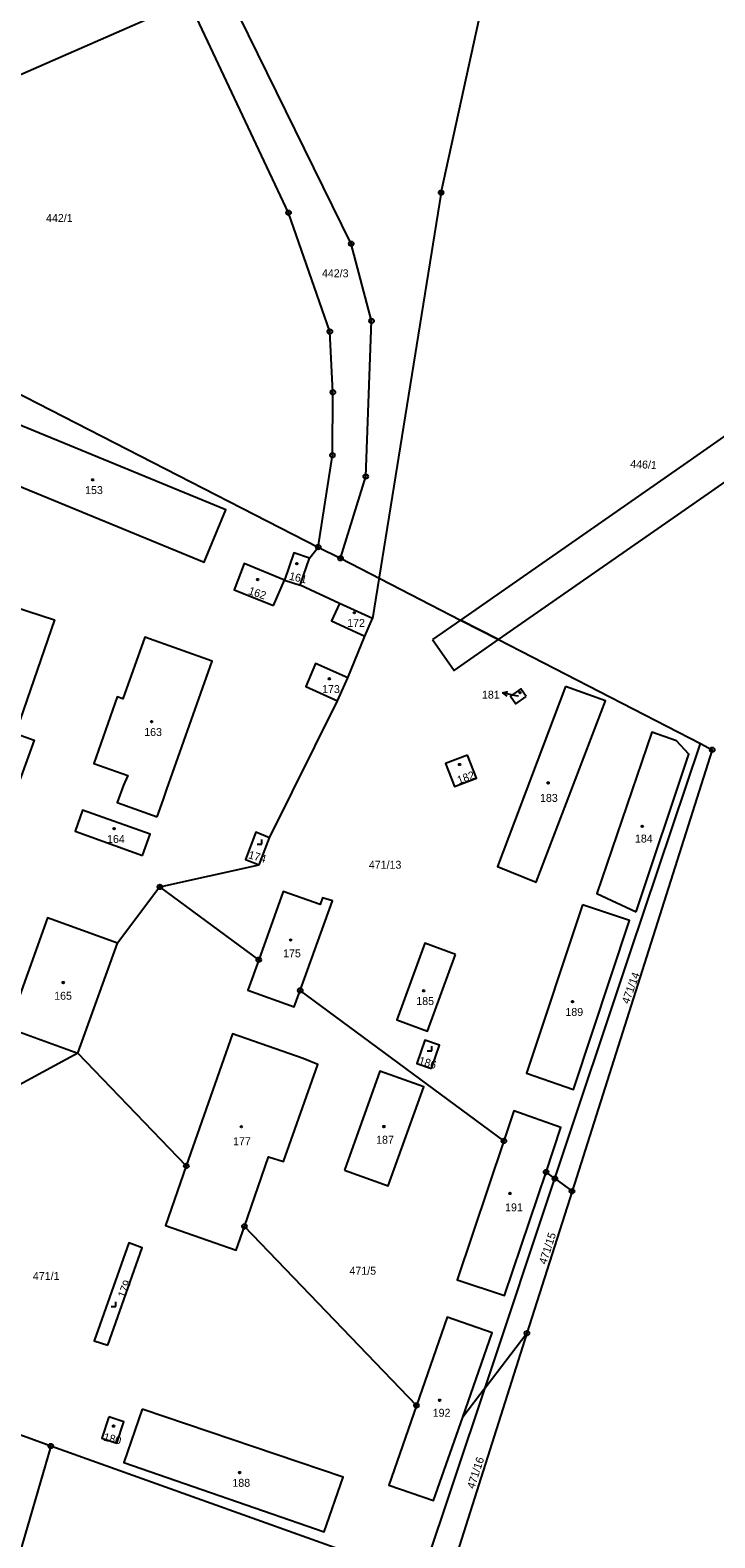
# Model space of a CAD drawing. Extents: x -758582 to -751794, y -998770 to -994350.
# Drawn here: x -753868 to -753721.4, y -996932.8 to -996610.1 of the extents above; entities that cross this region are included whole.
import ezdxf

# ---------------------------------------------------------------- set-up
doc = ezdxf.new("R2010")
doc.units = 0
for name, color, linetype in [('Hranice parcel', 7, 'Continuous'), ('Parcelní čísla', 7, 'Continuous'), ('Pop  PČ popisy', 7, 'Continuous'), ('Poz předměty', 7, 'Continuous'), ('Věcná břemena k části', 7, 'Continuous'), ('Značky bodu BP', 7, 'Continuous'), ('Značky budov', 7, 'Continuous'), ('Značky kultur', 7, 'Continuous')]:
    doc.layers.add(name, color=color, linetype=linetype)

msp = doc.modelspace()

# ---------------------------------------------------------------- linework, layer by layer
at = {"layer": 'Hranice parcel'}
for p, q in [((-753834.03, -996603.91), (-753942.18, -996651.11)), ((-753874.54, -996685.76), (-753806.31, -996720.72)), ((-753810.18, -996728.89), (-753808.19, -996723.09)), ((-753808.19, -996723.09), (-753806.31, -996720.72)), ((-753806.31, -996720.72), (-753801.53, -996723.13)), ((-753801.73, -996732.82), (-753810.18, -996728.89)), ((-753800.01, -996748.75), (-753796.35, -996739.83)), ((-753802.2, -996753.65), (-753800.01, -996748.75)), ((-753816.73, -996782.97), (-753802.2, -996753.65)), ((-753818.95, -996788.72), (-753816.73, -996782.97)), ((-753840.2, -996793.46), (-753818.95, -996788.72)), ((-753840.2, -996793.46), (-753849.28, -996805.48)), ((-753819.06, -996809.07), (-753840.2, -996793.46)), ((-753857.78, -996829.03), (-753849.28, -996805.48)), ((-753766.58, -996847.84), (-753810.18, -996815.63)), ((-753857.78, -996829.03), (-753878.25, -996840.12)), ((-753834.55, -996853.2), (-753857.78, -996829.03)), ((-753755.66, -996855.91), (-753757.56, -996854.5)), ((-753770.6, -996900.68), (-753755.66, -996855.91)), ((-753752, -996858.61), (-753761.65, -996888.99)), ((-753755.66, -996855.91), (-753752, -996858.61)), ((-753785.3, -996904.45), (-753822.12, -996866.13)), ((-753770.6, -996900.68), (-753761.65, -996888.99)), ((-753784.22, -996941.5), (-753770.6, -996900.68)), ((-753770.6, -996900.68), (-753775.4, -996906.94)), ((-753863.56, -996913.15), (-753870.24, -996936.23)), ((-753784.22, -996941.5), (-753863.56, -996913.15))]:
    msp.add_line(p, q, dxfattribs=at)
for points in [[(-753801.53, -996723.13), (-753796.14, -996705.63), (-753794.91, -996672.33), (-753799.24, -996655.8), (-753845.29, -996562.1), (-753839.59, -996551.34)], [(-753806.31, -996720.72), (-753803.27, -996701.08), (-753803.18, -996687.6), (-753803.83, -996674.61), (-753812.65, -996649.16), (-753834.03, -996603.91)], [(-753889.23, -996699.92), (-753830.74, -996723.97), (-753826.13, -996712.75), (-753884.62, -996688.69), (-753889.23, -996699.92)], [(-753808.19, -996723.09), (-753811.52, -996721.94), (-753813.53, -996727.81), (-753810.18, -996728.89)], [(-753815.91, -996733.25), (-753813.53, -996727.81), (-753822.14, -996724.23), (-753824.33, -996729.87), (-753815.91, -996733.25)], [(-753801.53, -996723.13), (-753775.87, -996736.35), (-753767.74, -996740.53), (-753724.52, -996762.8)], [(-753884.65, -996751.21), (-753884.11, -996749.42), (-753882.15, -996750.09), (-753879.74, -996743.09), (-753878.28, -996743.59), (-753874.47, -996732.5), (-753862.77, -996736.34), (-753870.13, -996757.67), (-753872.4, -996756.89), (-753873.24, -996759.88), (-753867.14, -996762.07), (-753871.44, -996774.09), (-753890.56, -996767.28), (-753889.05, -996763.12)], [(-753801.73, -996732.82), (-753803.46, -996736.51), (-753796.35, -996739.83)], [(-753796.35, -996739.83), (-753794.72, -996736), (-753801.73, -996732.82)], [(-753840.78, -996778.45), (-753839.44, -996774.66), (-753838.71, -996772.58), (-753829.04, -996745.13), (-753843.45, -996740.03), (-753848.12, -996753.2), (-753849.35, -996752.77), (-753854.33, -996767.03), (-753847.07, -996769.63), (-753847.97, -996771.66), (-753849.32, -996775.44), (-753840.78, -996778.45)], [(-753800.01, -996748.75), (-753806.89, -996745.62), (-753809, -996750.6), (-753802.2, -996753.65)], [(-753753.4, -996750.56), (-753767.96, -996789.12), (-753759.66, -996792.45), (-753744.81, -996753.64), (-753753.4, -996750.56)], [(-753761.8, -996752.7), (-753762.98, -996751.07), (-753765.18, -996752.66), (-753764, -996754.29), (-753761.8, -996752.7)], [(-753738.25, -996798.84), (-753726.99, -996765.04), (-753729.65, -996762.24), (-753734.9, -996760.37), (-753746.68, -996794.91), (-753738.25, -996798.84)], [(-753755.66, -996855.91), (-753739.54, -996807.6), (-753724.52, -996762.8)], [(-753724.52, -996762.8), (-753721.99, -996764.12), (-753752, -996858.61)], [(-753774.36, -996765.28), (-753779.06, -996767.05), (-753777.12, -996772.01), (-753772.44, -996770.18), (-753774.36, -996765.28)], [(-753843.9, -996786.74), (-753842.31, -996782.17), (-753856.75, -996777.05), (-753858.37, -996781.56), (-753843.9, -996786.74)], [(-753816.73, -996782.97), (-753819.68, -996781.74), (-753821.92, -996787.57), (-753818.95, -996788.72)], [(-753810.18, -996815.63), (-753803.29, -996796.45), (-753805.4, -996795.83), (-753805.91, -996797.21), (-753813.79, -996794.44), (-753819.06, -996809.07)], [(-753849.28, -996805.48), (-753864.25, -996800.1), (-753872.71, -996823.65), (-753857.78, -996829.03)], [(-753749.76, -996797.34), (-753761.74, -996833.37), (-753751.68, -996836.84), (-753739.69, -996800.65), (-753749.76, -996797.34)], [(-753776.95, -996807.95), (-753783.5, -996805.54), (-753789.49, -996821.95), (-753782.9, -996824.34), (-753776.95, -996807.95)], [(-753819.06, -996809.07), (-753821.41, -996815.58), (-753811.45, -996819.17), (-753810.18, -996815.63)], [(-753822.12, -996866.13), (-753816.97, -996851.21), (-753813.76, -996852.24), (-753806.38, -996831.47), (-753809.57, -996830.17), (-753824.66, -996824.95), (-753834.55, -996853.2)], [(-753782.06, -996832.36), (-753780.37, -996827.33), (-753783.51, -996826.25), (-753785.19, -996831.3), (-753782.06, -996832.36)], [(-753800.73, -996854.07), (-753791.36, -996857.48), (-753783.68, -996836.29), (-753793.1, -996832.88), (-753800.73, -996854.07)], [(-753757.56, -996854.5), (-753754.36, -996844.96), (-753764.42, -996841.43), (-753766.58, -996847.84)], [(-753766.58, -996847.84), (-753776.59, -996877.54), (-753766.46, -996880.94), (-753757.56, -996854.5)], [(-753834.55, -996853.2), (-753839, -996865.93), (-753823.88, -996871.2), (-753822.12, -996866.13)], [(-753851.32, -996891.54), (-753844.03, -996870.73), (-753846.87, -996869.65), (-753854.29, -996890.65), (-753851.32, -996891.54)], [(-753775.4, -996906.94), (-753769.11, -996888.89), (-753778.74, -996885.54), (-753785.3, -996904.45)], [(-753761.65, -996888.99), (-753778.93, -996943.39), (-753784.22, -996941.5)], [(-753863.56, -996913.15), (-753868.62, -996911.34), (-753884.21, -996905.77), (-753901.63, -996899.54)], [(-753851.17, -996906.89), (-753852.67, -996911.46), (-753849.43, -996912.52), (-753847.91, -996907.94), (-753851.17, -996906.89)], [(-753844, -996905.26), (-753847.9, -996916.68), (-753805.03, -996931.54), (-753801, -996919.82), (-753844, -996905.26)], [(-753785.3, -996904.45), (-753791.2, -996921.49), (-753781.61, -996924.78), (-753775.4, -996906.94)]]:
    msp.add_lwpolyline(points, dxfattribs=at)
at = {"layer": 'Pop  PČ popisy'}
for p, q in [((-753766.85, -996751.96), (-753765.77, -996751.67)), ((-753763.92, -996752.58), (-753766.85, -996751.96)), ((-753766.85, -996751.96), (-753765.98, -996752.65)), ((-753763.48, -996752.67), (-753763.92, -996752.58))]:
    msp.add_line(p, q, dxfattribs=at)
at = {"layer": 'Poz předměty'}
for q in [(-753761.33, -996559.87), (-753794.72, -996736)]:
    msp.add_line((-753780.02, -996644.86), q, dxfattribs=at)
for radius in [0.5, 0.4, 0.3, 0.2, 0.1]:
    msp.add_circle((-753780.02, -996644.86), radius, dxfattribs=at)
at = {"layer": 'Věcná břemena k části'}
for points in [[(-753775.87, -996736.35), (-753767.74, -996740.53), (-753722.77, -996709.26), (-753644.07, -996654.17), (-753591.01, -996617.57), (-753595.6, -996610.92), (-753648.69, -996647.53), (-753727.39, -996702.64)], [(-753781.83, -996740.49), (-753777.22, -996747.12), (-753767.74, -996740.53), (-753775.87, -996736.35)]]:
    msp.add_lwpolyline(points, close=True, dxfattribs=at)
at = {"layer": 'Značky bodu BP'}
for centre, radius in [((-753812.65, -996649.16), 0.5), ((-753812.65, -996649.16), 0.0303), ((-753799.24, -996655.8), 0.5), ((-753799.24, -996655.8), 0.0303), ((-753803.83, -996674.61), 0.5), ((-753803.83, -996674.61), 0.0303), ((-753794.91, -996672.33), 0.5), ((-753794.91, -996672.33), 0.0303), ((-753803.18, -996687.6), 0.5), ((-753803.18, -996687.6), 0.0303), ((-753803.27, -996701.08), 0.5), ((-753803.27, -996701.08), 0.0303), ((-753796.14, -996705.63), 0.5), ((-753796.14, -996705.63), 0.0303), ((-753806.31, -996720.72), 0.5), ((-753806.31, -996720.72), 0.0303), ((-753801.53, -996723.13), 0.5), ((-753801.53, -996723.13), 0.0303), ((-753721.99, -996764.12), 0.5), ((-753721.99, -996764.12), 0.0303), ((-753840.2, -996793.46), 0.5), ((-753840.2, -996793.46), 0.0303), ((-753819.06, -996809.07), 0.5), ((-753819.06, -996809.07), 0.0303), ((-753810.18, -996815.63), 0.5), ((-753810.18, -996815.63), 0.0303), ((-753766.58, -996847.84), 0.5), ((-753766.58, -996847.84), 0.0303), ((-753834.55, -996853.2), 0.5), ((-753834.55, -996853.2), 0.0303), ((-753757.56, -996854.5), 0.5), ((-753757.56, -996854.5), 0.0303), ((-753755.66, -996855.91), 0.5), ((-753755.66, -996855.91), 0.0303), ((-753752, -996858.61), 0.5), ((-753752, -996858.61), 0.0303), ((-753822.12, -996866.13), 0.5), ((-753822.12, -996866.13), 0.0303), ((-753761.65, -996888.99), 0.5), ((-753761.65, -996888.99), 0.0303), ((-753785.3, -996904.45), 0.5), ((-753785.3, -996904.45), 0.0303), ((-753863.56, -996913.15), 0.5), ((-753863.56, -996913.15), 0.0303)]:
    msp.add_circle(centre, radius, dxfattribs=at)
at = {"layer": 'Značky budov'}
for centre in [(-753854.58, -996706.34), (-753810.91, -996724.27), (-753819.28, -996727.69), (-753798.59, -996734.77), (-753803.93, -996748.93), (-753763.12, -996751.91), (-753841.97, -996758.12), (-753776.07, -996767.27), (-753757.1, -996771.21), (-753850.01, -996781.02), (-753736.97, -996780.5), (-753812.2, -996804.85), (-753860.9, -996813.94), (-753783.75, -996815.7), (-753751.88, -996818.03), (-753822.77, -996844.78), (-753792.26, -996844.76), (-753765.29, -996859.08), (-753780.33, -996903.33), (-753850.13, -996908.88), (-753823.14, -996918.82)]:
    msp.add_circle(centre, 0.175, dxfattribs=at)
at = {"layer": 'Značky kultur'}
for p, q in [((-753819.42, -996784.33), (-753818.42, -996784.33)), ((-753818.42, -996784.33), (-753818.42, -996783.33)), ((-753783.01, -996828.54), (-753782.01, -996828.54)), ((-753782.01, -996828.54), (-753782.01, -996827.54)), ((-753850.65, -996883.27), (-753849.65, -996883.27)), ((-753849.65, -996883.27), (-753849.65, -996882.27))]:
    msp.add_line(p, q, dxfattribs=at)

# ---------------------------------------------------------------- texts
at = {"layer": 'Parcelní čísla'}
for s, p in [('442/1', (-753864.57, -996651.15)), ('442/3', (-753805.52, -996662.99)), ('153', (-753856.21, -996709.39)), ('172', (-753800.12, -996737.82)), ('173', (-753805.48, -996751.98)), ('181', (-753771.27, -996753.18)), ('163', (-753843.56, -996761.17)), ('183', (-753758.84, -996775.27)), ('164', (-753851.52, -996784.07)), ('184', (-753738.52, -996783.97)), ('471/13', (-753795.48, -996789.58)), ('175', (-753813.83, -996808.53)), ('165', (-753862.83, -996817.62)), ('185', (-753785.33, -996818.75)), ('189', (-753753.41, -996821.08)), ('177', (-753824.55, -996848.76)), ('187', (-753793.92, -996848.44)), ('191', (-753766.32, -996862.91)), ('471/5', (-753799.62, -996876.48)), ('471/1', (-753867.39, -996877.6)), ('192', (-753781.81, -996906.87)), ('188', (-753824.69, -996921.87))]:
    msp.add_text(s, height=1.7, dxfattribs=at).set_placement(p)
for s, rotation, p in [('446/1', 357, (-753739.57, -996703.76)), ('161', 347, (-753812.67, -996727.69)), ('162', 341, (-753821.41, -996730.76)), ('182', 20, (-753776.22, -996771.5)), ('174', 344, (-753821.41, -996787.31)), ('471/14', 70, (-753739.84, -996818.65)), ('186', 343, (-753784.96, -996831.36)), ('471/15', 72, (-753757.53, -996874.39)), ('179', 68, (-753847.73, -996881.58)), ('180', 346, (-753852.41, -996911.95)), ('471/16', 72, (-753772.92, -996922.44))]:
    msp.add_text(s, height=1.7, rotation=rotation, dxfattribs=at).set_placement(p)

doc.saveas('drawing.dxf')
